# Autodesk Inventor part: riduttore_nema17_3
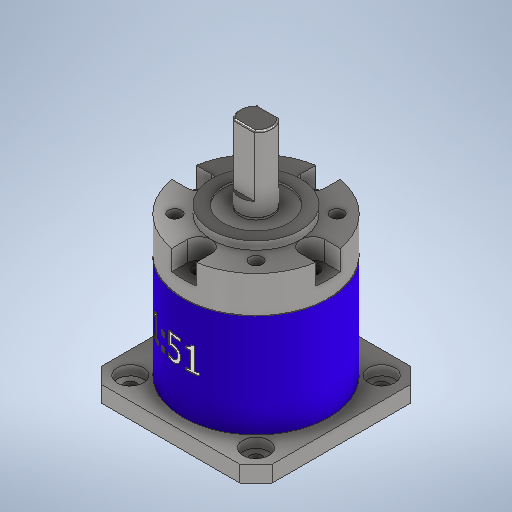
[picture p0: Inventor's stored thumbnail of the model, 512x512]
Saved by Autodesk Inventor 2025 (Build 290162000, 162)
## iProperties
Created: 2026-01
Part Number: riduttore_nema17_3
Material: Acciaio inossidabile
Document SubType Name: Modeling
Designer: R5800u
Density: 8 g/cm^3
Appearance: Semilucidato
Mass: 320.505 g
Surface Area: 104.528 cm^2
Volume: 40.0631 cm^3
Author: R5800u
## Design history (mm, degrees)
sketch "Schizzo1"
  geometry: L1 (21, 21)-(-21, 21); L2 (-21, 21)-(-21, -21); L3 (-21, -21)-(21, -21); L4 (21, -21)-(21, 21); L5 (21, 21)-(-21, -21); L6 (-21, 21)-(21, -21); 1 further point
  constraints: 12 end point, 2 midpoint, 2 parallel, 1 horizontal, 1 perpendicular
  dimensions: "d0" = 42 distance of L3.end L2.end; "d1" = 42 distance of L2.end L1.end
extrude "Estrusione1" new body sketch "Schizzo1" distance "d2" = 4; taper "d3" = 0 deg
sketch "Schizzo2"
  geometry: C1 r 18 at (0, 0); 1 further point
  constraints: 1 centre point, 1 coincident
  dimensions: "d4" = 36 diameter of C1
extrude "Estrusione2" join sketch "Schizzo2" distance "d5" = 34.5; taper "d6" = 0 deg
sketch "Schizzo3"
  geometry: C1 r 11 at (0, 0); 1 further point
  constraints: 1 centre point, 1 coincident
  dimensions: "d7" = 22 diameter of C1
extrude "Estrusione3" join sketch "Schizzo3" distance "d8" = 2; taper "d9" = 0 deg
sketch "Schizzo4"
  geometry: C1 r 4 at (0, 0); 1 further point
  constraints: 1 centre point, 1 coincident
  dimensions: "d10" = 8 diameter of C1
extrude "Estrusione4" new body sketch "Schizzo4" distance "d11" = 18.5; taper "d12" = 0 deg
sketch "Schizzo5"
  geometry: L1 (7.554, -3)-(-7.554, -3); L2 (-7.554, -3)-(-7.554, 3); L3 (-7.554, 3)-(7.554, 3); L4 (7.554, 3)-(7.554, -3); L5 (7.554, -3)-(-7.554, 3); L6 (-7.554, -3)-(7.554, 3); C1 r 4 at (0, 0) reference; 5 further points
  constraints: 12 end point, 2 midpoint, 2 parallel, 1 horizontal, 1 perpendicular
  dimensions: "d13" = 6 distance of L1.end L2.end
extrude "Estrusione5" cut sketch "Schizzo5" distance "d14" = 15; taper "d15" = 0 deg
sketch "Schizzo6"
  geometry: L1 (-14, -3)-(-17.748, -3); L2 (-14, 3)-(-17.748, 3); A1 r 3 centre (-14, 0) between (-14, -3) and (-14, 3); A2 r 18 centre (0, 0) between (-17.748, -3) and (-17.748, 3) reference; 1 further point
  constraints: 4 end point, 4 point on circle, 2 tangent, 1 centre point, 1 horizontal, 1 parallel
  dimensions: "d16" = 6 diameter of A1; "d17" = 14 distance of point (0, 0) A1.centre
extrude "Estrusione6" cut sketch "Schizzo6" distance "d18" = 5; taper "d19" = 0 deg
pattern_circular "Serie circolare1" dims angle "d21" = 360 deg
sketch "Schizzo7"
  geometry: L1 (10, -10)-(-10, -10); L2 (-10, -10)-(-10, 10); L3 (-10, 10)-(10, 10); L4 (10, 10)-(10, -10); L5 (10, -10)-(-10, 10); L6 (-10, -10)-(10, 10); C1 r 4 at (0, 0) reference; 1 further point
  constraints: 12 end point, 2 midpoint, 2 parallel, 1 horizontal, 1 perpendicular
  dimensions: "d23" = 20 distance of L2.end L3.end; "d24" = 20 distance of L1.end L2.end
hole "Foro1" sketch "Schizzo7" at (-10, 10), (-10, -10), (10, -10), (10, 10) diameter "d25" = 3.2; stored, may be unused: countersink angle "d29" = 90 deg, drill point angle "d31" = 118 deg; dims "d26" = 6, "d27" = 6.5, "d28" = 3.4, "d30" = 10
sketch "Schizzo8"
  geometry: A1 r 3 centre (-14, 0) between (-14, -3) and (-14, 3) reference; 1 further point
hole "Foro2" sketch "Schizzo8" at (-14, 0) diameter "d32" = 3.2; stored, may be unused: countersink angle "d36" = 90 deg, drill point angle "d38" = 118 deg; dims "d33" = 6, "d34" = 4, "d35" = 2, "d37" = 10
pattern_circular "Serie circolare2" dims angle "d40" = 360 deg
node "Piano di lavoro1"
sketch "Schizzo9"
  geometry: C1 r 17.9 at (0, 0); A1 r 18 centre (0, 0) between (3, -17.748) and (17.748, -3) reference; A2 r 18 centre (0, 0) between (3, -17.748) and (17.748, -3) reference; 1 further point
  constraints: 1 centre point
  dimensions: "d43" = 0.1 radial gap between concentric circles of A2 C1
extrude "Estrusione7" cut sketch "Schizzo9" distance "d44" = 0.1; taper "d45" = 0 deg
chamfer "Smusso1" distance "d46" = 4; stored, may be unused: second distance "d47" = 2, angle "d48" = 45 deg
sketch "Schizzo10"
  geometry: L1 (15.5, -15.5)-(-15.5, -15.5); L2 (-15.5, -15.5)-(-15.5, 15.5); L3 (-15.5, 15.5)-(15.5, 15.5); L4 (15.5, 15.5)-(15.5, -15.5); L5 (15.5, -15.5)-(-15.5, 15.5); L6 (-15.5, -15.5)-(15.5, 15.5); C1 r 4 at (0, 0) reference; 1 further point
  constraints: 12 end point, 2 midpoint, 2 parallel, 1 horizontal, 1 perpendicular
  dimensions: "d49" = 31 distance of L2.end L3.end; "d50" = 31 distance of L1.end L2.end
hole "Foro3" sketch "Schizzo10" at (15.5, -15.5), (15.5, 15.5), (-15.5, 15.5), (-15.5, -15.5) diameter "d51" = 3.2; stored, may be unused: countersink angle "d55" = 90 deg, drill point angle "d57" = 118 deg; dims "d52" = 6, "d53" = 6.5, "d54" = 2.4, "d56" = 10
sketch "Schizzo11"
  geometry: C1 r 4 at (0, 0) reference; C2 r 8 at (0, 0); 1 further point
  constraints: 1 centre point, 1 coincident
  dimensions: "d58" = 16 diameter of C2
extrude "Estrusione8" cut sketch "Schizzo11" distance "d59" = 0.5; taper "d60" = 0 deg
fillet "Raccordo1" dims "d61" = 0.4
feature "Filettatura1" dims "d62" = 10, "d63" = 0
feature "Filettatura2" dims "d64" = 10, "d65" = 0
feature "Filettatura3" dims "d66" = 10, "d67" = 0
feature "Filettatura4" dims "d68" = 10, "d69" = 0
feature "Filettatura5" dims "d70" = 10, "d71" = 0
feature "Filettatura6" dims "d72" = 10, "d73" = 0
feature "Filettatura7" dims "d74" = 10, "d75" = 0
feature "Filettatura8" dims "d76" = 10, "d77" = 0
feature "Filettatura9" dims "d78" = 4, "d79" = 0
feature "Filettatura10" dims "d80" = 4, "d81" = 0
feature "Filettatura11" dims "d82" = 4, "d83" = 0
feature "Filettatura12" dims "d84" = 4, "d85" = 0
sketch "Schizzo12"
  geometry: C1 r 4 at (0, 0) reference; C2 r 11 at (0, 0); 1 further point
  constraints: 1 centre point, 1 coincident
  dimensions: "d86" = 22 diameter of C2
extrude "Estrusione9" cut sketch "Schizzo12" distance "d87" = 2.5; taper "d88" = 0 deg
sketch "Schizzo13"
  geometry: C1 r 4 at (0, 0) reference; C2 r 5 at (0, 0); 1 further point
  constraints: 1 centre point, 1 coincident
  dimensions: "d89" = 10 diameter of C2
extrude "Estrusione10" cut sketch "Schizzo13" distance "d90" = 9.5; taper "d91" = 0 deg
node "Piano di lavoro2"
sketch "Schizzo14"
  geometry: L1 (4.854, 20.491)-(30.975, 20.491); L2 (30.975, 20.491)-(30.975, 11.776); L3 (30.975, 11.776)-(4.854, 11.776); L4 (4.854, 11.776)-(4.854, 20.491); 1 further point
  constraints: 2 other
feature "Sbalzo1" sketch "Schizzo14" dims "d93" = 0.1, "d94" = 0
node "Solido1"
node "Solido2"
node "Linea chiusa proiettata1"
other parameters: "d42" = -9, "d92" = 0
